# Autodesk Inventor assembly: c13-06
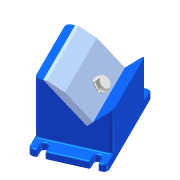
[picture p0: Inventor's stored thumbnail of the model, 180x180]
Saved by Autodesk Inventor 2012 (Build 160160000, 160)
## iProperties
Created: 2010-11
Part Number: c13-06
Document SubType Name: Assembly
Designer: Beta-8540w
Author: Beta-8540w
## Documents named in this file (5)
- C:\Users\VMuser\Desktop\Inventor 2012 Essentials\Assemblies\Chapter 13\c13-06.iam
- C:\Users\VMuser\Desktop\Inventor 2012 Essentials\Content Center Files\en-US\ISO 4017\ISO 4017 - M10 x 35ISO.ipt
- C:\Users\VMuser\Desktop\Inventor 2012 Essentials\Parts\Chapter 13\c13-02.ipt
- C:\Users\VMuser\Desktop\Inventor 2012 Essentials\Content Center Files\en-US\ISO 7091\ISO 7091 - ST 10 - 100 HV.ipt
- C:\Users\VMuser\Desktop\Inventor 2012 Essentials\Parts\Chapter 13\c13-01.ipt
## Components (4 placed, 4 different names)
1. c13-01:1 — Insert:1, Angle:1
2. c13-02:1 — Insert:1, Angle:1, Insert:2
3. ISO 4017 M10 x 35:1 — Insert:3, Bolt Angle
4. ISO 7091 ST 10 - 100 HV:1 — Insert:2, Insert:3
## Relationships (5: Insert 3, Angle 2)
- Insert:1: c13-01:1 ↔ c13-02:1
- Angle:1: c13-01:1 ↔ c13-02:1
- Insert:2: c13-02:1 ↔ ISO 7091 ST 10 - 100 HV:1
- Insert:3: ISO 4017 M10 x 35:1 ↔ ISO 7091 ST 10 - 100 HV:1
- Bolt Angle [Angle]: ISO 4017 M10 x 35:1
